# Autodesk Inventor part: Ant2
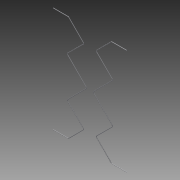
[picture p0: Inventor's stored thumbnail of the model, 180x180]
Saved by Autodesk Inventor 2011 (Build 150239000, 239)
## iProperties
Created: 2014-02
Part Number: Ant2
Document SubType Name: Modeling
Designer: Evgeny
Density: 1 g/cm^3
Author: Evgeny
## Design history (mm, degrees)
sketch "Эскиз1"
  geometry: L1 (17.195, 3.523)-(115.176, 102.173); L2 (115.156, 109.24)-(32.234, 191.798); L3 (32.214, 198.865)-(108.973, 276.148); L4 (112.521, 277.624)-(191.44, 277.624); L5 (17.195, -3.523)-(115.176, -102.173); L6 (115.156, -109.24)-(32.234, -191.798); L7 (32.214, -198.865)-(108.973, -276.148); L8 (112.521, -277.624)-(191.44, -277.624); L9 (-22.565, -3.523)-(-120.546, -102.173); L10 (-120.526, -109.24)-(-37.605, -191.798); L11 (-37.585, -198.865)-(-114.344, -276.148); L12 (-117.892, -277.624)-(-196.811, -277.624); L13 (-22.565, 3.523)-(-120.546, 102.173); L14 (-120.526, 109.24)-(-37.605, 191.798); L15 (-37.585, 198.865)-(-114.344, 276.148); L16 (-117.892, 277.624)-(-196.811, 277.624); A1 r 5 centre (112.521, 272.624) between (112.521, 277.624) and (108.973, 276.148); A2 r 5 centre (35.762, 195.341) between (32.214, 198.865) and (32.234, 191.798); A3 r 5 centre (111.628, 105.697) between (115.176, 102.173) and (115.156, 109.24); A4 r 5 centre (20.742, 0) between (17.195, 3.523) and (17.195, -3.523); A5 r 5 centre (111.628, -105.697) between (115.156, -109.24) and (115.176, -102.173); A6 r 5 centre (35.762, -195.341) between (32.234, -191.798) and (32.214, -198.865); A7 r 5 centre (112.521, -272.624) between (108.973, -276.148) and (112.521, -277.624); A8 r 5 centre (-117.892, -272.624) between (-117.892, -277.624) and (-114.344, -276.148); A9 r 5 centre (-41.132, -195.341) between (-37.585, -198.865) and (-37.605, -191.798); A10 r 5 centre (-116.999, -105.697) between (-120.546, -102.173) and (-120.526, -109.24); A11 r 5 centre (-26.113, 0) between (-22.565, -3.523) and (-22.565, 3.523); A12 r 5 centre (-116.999, 105.697) between (-120.526, 109.24) and (-120.546, 102.173); A13 r 5 centre (-41.132, 195.341) between (-37.605, 191.798) and (-37.585, 198.865); A14 r 5 centre (-117.892, 272.624) between (-114.344, 276.148) and (-117.892, 277.624); 19 further points
  constraints: 32 end point, 28 point on circle, 28 point on line, 28 tangent, 14 centre point, 10 equal radius, 6 parallel, 1 coincident, 1 horizontal
  dimensions: "d0" = 13.695 distance of point (13.695, 0) point (0, 0); "d1" = 34.695 distance of point (-21, 0) point (13.695, 0); "d2" = 149 distance of point (13.695, 0) point (118.695, 105.717); "d3" = 127 distance of point (118.695, 105.717) point (28.695, 195.321); "d4" = 116 distance of point (28.695, 195.321) point (110.44, 277.624); "d5" = 81 distance of point (110.44, 277.624) L4.end; "d6" = 105 horizontal distance of point (13.695, 0) point (118.695, 105.717); "d7" = 15 horizontal distance of point (13.695, 0) point (28.695, 195.321); "d9" = 5 radius of A1; "d10" = 149 distance of point (13.695, 0) point (118.695, -105.717); "d11" = 127 distance of point (118.695, -105.717) point (28.695, -195.321); "d12" = 116 distance of point (28.695, -195.321) point (110.44, -277.624); "d13" = 81 distance of point (110.44, -277.624) L8.end; "d14" = 105 horizontal distance of point (13.695, 0) point (118.695, -105.717); "d15" = 15 horizontal distance of point (13.695, 0) point (28.695, -195.321); "d16" = 5 radius of A4; "d17" = 34.875 distance of point (15.809, 0) point (-19.066, 0); "d18" = 149 distance of point (-19.066, 0) point (-124.066, -105.717); "d19" = 127 distance of point (-124.066, -105.717) point (-34.066, -195.321); "d20" = 116 distance of point (-34.066, -195.321) point (-115.811, -277.624); "d21" = 81 distance of point (-115.811, -277.624) L12.end; "d22" = 105 horizontal distance of point (-19.066, 0) point (-124.066, -105.717); "d23" = 15 horizontal distance of point (-19.066, 0) point (-34.066, -195.321); "d24" = 96.74497 horizontal distance of point (-19.066, 0) point (-115.811, -277.624) (derived); "d25" = 5 radius of A8; "d26" = 149 distance of point (-19.066, 0) point (-124.066, 105.717); "d27" = 127 distance of point (-124.066, 105.717) point (-34.066, 195.321); "d28" = 116 distance of point (-34.066, 195.321) point (-115.811, 277.624); "d29" = 81 distance of point (-115.811, 277.624) L16.end; "d30" = 105 horizontal distance of point (-19.066, 0) point (-124.066, 105.717); "d31" = 15 horizontal distance of point (-19.066, 0) point (-34.066, 195.321); "d32" = 5 radius of A11
node "РабПлоскость1"
sketch "Эскиз2"
  geometry: C1 r 1.5 at (0, 0); 1 further point
  constraints: 1 centre point
  dimensions: "d33" = 3 diameter of C1
feature "Сдвиг1" sketch "Эскиз2" dims "d34" = 0
node "РабПлоскость2"
sketch "Эскиз3"
  geometry: C1 r 1.5 at (0, 0); 1 further point
  constraints: 1 centre point
  dimensions: "d35" = 3 diameter of C1
feature "Сдвиг2" sketch "Эскиз3" dims "d36" = 0
node "Твердое тело1"
